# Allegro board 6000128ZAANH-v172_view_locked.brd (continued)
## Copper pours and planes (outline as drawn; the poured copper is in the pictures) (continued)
VDD_B on L4 (solid shape): 87.38,23.75 87.38,21.72 87.25,21.59 85.98,21.59 85.85,21.72 85.85,23.75 85.98,23.88 87.25,23.88
VDD_B on L5: 72.77,33.15 76.33,33.15 76.58,32.89 76.58,29.84 78.17,28.26 86.04,28.26 87.63,26.67 87.63,21.72 87.25,21.34 83.31,21.34 82.93,21.72 82.93,23.37 82.3,24 75.63,24 72.52,27.11 72.52,32.89
VSS on TOP (solid shape): 78.93,40.01 78.93,39.05 78.68,38.8 78.68,37.4 78.55,37.27 77.53,37.27 77.34,37.47 77.34,39.88 77.6,40.13 78.8,40.13
VSS on TOP (solid shape): 84.45,35.62 84.45,32 83.7,31.24 83.7,28.32 83.57,28.19 78.74,28.19 78.62,28.32 78.62,31.3 77.85,32.06 77.85,33.07 78.18,33.4 81.92,33.4 83.57,35.05 83.57,35.62 83.63,35.69 84.39,35.69
VSS on BOTTOM (solid shape): 82.49,20.45 87.25,20.45 87.38,20.32 87.38,17.65 87.19,17.46 76.26,17.46 76.01,17.72 76.01,19.94 76.2,20.13 78.49,20.13 78.74,20.38 78.74,20.64 78.87,20.76 82.17,20.76
VSS on L4 (solid shape): 87.38,20.32 87.38,18.29 87.25,18.16 85.98,18.16 85.85,18.29 85.85,20.32 85.98,20.45 87.25,20.45
VSS on BOTTOM, L2, L3, L4, L5: 77.34,39.88 77.34,37.47 77.53,37.27 83.18,37.27 83.57,36.88 83.57,35.05 81.92,33.4 78.87,33.4 78.61,33.15 78.61,29.84 78.8,29.65 84.26,29.65 84.46,29.85 84.46,40.19 84.38,40.26 77.72,40.26
VSS on L3: 78.61,30.23 84.45,30.23 84.45,21.46 84.96,20.95 87.38,20.95 87.63,20.7 87.63,17.65 87.38,17.4 81.66,17.4 80.52,18.54 80.52,25.65 78.61,27.56
EAR_GND on TOP (solid shape): 27.37,40.32 27.37,38.73 27.24,38.61 23.3,38.61 23.18,38.73 23.18,40.32 23.3,40.45 27.24,40.45
EAR_GND on TOP (solid shape): 31.11,61.15 31.11,59.69 30.92,59.5 29.78,59.5 29.59,59.69 29.59,61.15 29.78,61.34 30.92,61.34
EAR_GND on BOTTOM (solid shape): 31.37,61.09 31.37,36.45 31.24,36.32 29.97,36.32 28.07,38.23 21.34,38.23 20.07,39.5 20.07,43.56 20.32,43.82 22.22,43.82 22.48,43.56 22.48,41.4 23.37,40.51 28.7,40.51 29.84,41.66 29.84,58.36 28.38,59.82 26.16,59.82 22.29,55.94 20.51,55.94 20.19,56.26 20.19,57.02 20.45,57.28 21.59,57.28 25.65,61.34 31.11,61.34
MAIN_3V3 on TOP (solid shape): 40.01,65.53 39.88,65.41 39.18,65.41 39.05,65.53 39.05,68.63 40.01,68.63
PAIR12_FB23 on TOP (solid shape): 38.28,37.14 38.28,35.99 38.23,35.94 37.02,35.94 36.89,36.07 36.89,37.09 37.02,37.21 38.2,37.21
PAIR12_FB23 on BOTTOM (solid shape): 37.53,37.09 37.53,35.05 37.4,34.92 36.51,34.92 36.39,35.05 36.39,37.09 36.51,37.21 37.4,37.21
PAIR36_FB22 on TOP (solid shape): 38.28,43.74 38.28,42.6 38.23,42.55 37.02,42.55 36.89,42.67 36.89,43.69 37.02,43.82 38.2,43.82
PAIR36_FB22 on BOTTOM (solid shape): 37.53,43.69 37.53,41.79 37.4,41.66 36.51,41.66 36.39,41.79 36.39,43.69 36.51,43.82 37.4,43.82
PAIR45_FB21 on TOP (solid shape): 38.28,50.35 38.28,49.2 38.23,49.15 37.02,49.15 36.89,49.28 36.89,50.29 37.02,50.42 38.2,50.42
PAIR45_FB21 on BOTTOM (solid shape): 37.53,50.29 37.53,48.39 37.4,48.26 36.51,48.26 36.39,48.39 36.39,50.29 36.51,50.42 37.4,50.42
PAIR78_FB20 on TOP (solid shape): 38.28,56.95 38.28,55.81 38.23,55.76 37.02,55.76 36.89,55.88 36.89,56.9 37.02,57.03 38.2,57.03
PAIR78_FB20 on BOTTOM (solid shape): 37.53,56.9 37.53,54.99 37.4,54.87 36.51,54.87 36.39,54.99 36.39,56.9 36.51,57.03 37.4,57.03
POWER_IN on BOTTOM (solid shape): 93.15,70.8 93.15,66.48 93.09,66.42 91.57,66.42 91.38,66.23 88.71,66.23 88.39,66.55 88.39,70.74 88.65,70.99 92.96,70.99
POWER_IN on L2: 88.14,81.52 91.44,81.52 91.44,68.07 91.19,67.82 88.52,67.82 88.14,68.2
N5320670 on TOP (solid shape): 49.72,68.26 49.85,68.14 49.85,67.69 49.72,67.56 49.21,67.56 49.21,68.33 48.91,68.63 49.72,68.63
N17419443 on BOTTOM (solid shape): 91.5,65.41 93.09,65.41 93.15,65.34 93.15,63.18 93.09,63.12 91.76,63.12 91.69,63.18 91.69,63.88 91.38,64.2 88.96,64.2 88.84,64.33 88.84,65.47 88.96,65.6 91.31,65.6
N17426803 on BOTTOM (solid shape): 64.33,24.26 64.33,23.3 64.26,23.24 62.29,23.24 62.04,22.99 62.04,19.11 62.23,18.92 65.41,18.92 65.72,19.24 65.72,20.57 65.85,20.7 66.74,20.7 67.31,20.13 73.41,20.13 73.6,19.94 73.6,17.72 73.41,17.53 61.59,17.53 61.02,18.1 61.02,23.62 61.72,24.32 64.26,24.32
N17426807 on BOTTOM (solid shape): 65.6,27.69 65.6,25.46 66.48,24.57 73.41,24.57 73.6,24.38 73.6,22.03 73.47,21.91 67.31,21.91 66.74,21.34 62.42,21.34 62.29,21.46 62.29,22.54 62.36,22.61 64.33,22.61 64.58,22.86 64.58,26.92 64.33,27.18 62.36,27.18 62.29,27.24 62.29,28.32 62.36,28.38 64.9,28.38
N17432429 on BOTTOM (solid shape): 84.33,77.09 84.33,73.66 84.2,73.53 80.2,73.53 80.07,73.66 80.07,74.87 79.63,75.31 72.01,75.31 70.99,74.3 64.52,74.3 64.14,74.68 64.14,77.85 64.39,78.11 83.31,78.11
N17432448 on TOP (solid shape): 68.9,72.83 68.9,68.45 68.77,68.33 64.9,68.33 64.77,68.45 64.77,72.83 65.02,73.09 68.64,73.09
N17432448 on BOTTOM (solid shape): 71.88,70.99 73.53,70.99 73.66,70.87 73.66,69.72 73.53,69.6 64.39,69.6 64.26,69.72 64.26,72.71 64.64,73.09 69.79,73.09
N17432547 on BOTTOM (solid shape): 73.47,72.52 72.07,72.52 72.07,74.68 73.47,74.68
N17432813 on TOP (solid shape): 86.74,70.87 86.74,66.93 86.61,66.8 82.42,66.8 82.17,67.06 82.17,70.87 82.42,71.12 86.49,71.12
N17432813 on BOTTOM (solid shape): 84.33,72.9 84.33,70.87 84.71,70.48 86.49,70.48 86.74,70.23 86.74,66.67 86.49,66.42 80.9,66.42 80.77,66.55 80.77,72.9 80.9,73.03 84.2,73.03
N17439510 on TOP (solid shape): 71.38,40.9 71.12,40.64 66.04,40.64 65.79,40.39 65.79,39.62 65.47,39.31 63.75,39.31 63.63,39.43 63.63,44.07 63.75,44.2 67.64,44.2 69.09,45.65 69.09,47.81 69.79,48.5 69.79,51.69 71.38,51.69
N17439514 on TOP (solid shape): 82.49,46.1 82.49,44.39 82.11,44.01 81.41,44.01 80.14,42.74 77.47,42.74 77.41,42.8 77.41,44.58 77.47,44.64 78.8,44.64 79.12,44.96 79.12,46.03 79.25,46.15 82.43,46.15
N17439696 on TOP (solid shape): 83.82,51.56 83.82,49.53 84.52,48.83 85.47,48.83 85.53,48.77 85.53,48.2 85.47,48.13 84.14,48.13 83.76,48.51 72.39,48.51 72.39,51.69 83.69,51.69
N17439883 on TOP (solid shape): 78.36,47.74 78.36,45.59 78.17,45.4 74.1,45.4 73.15,44.45 72.01,44.45 71.88,44.57 71.88,47.82 71.95,47.88 78.22,47.88

Small or netless copper shapes (teardrops, artwork), in the pictures only: 4 on BOTTOM, 6 on TOP, 4 on L4

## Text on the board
Ref Des/Silkscreen Bottom: + | -
User.Comments: CR_3_1 | 3_5.5_3_G5.5 | 3.9_4.9_3.9_G7 | 4.7_5.3_4.7_G6.5 | The Layout file released by Mitrastar to | TI | Deliver data time: 2024/08/21 | MSTC confidential information and must be deleted in one-day after the review process is done. | to any third party without Mitrastar's prior written approval. | whether direct or indirect, suffered by Mitrastar. | shall not use or modify such Layout file for | Vender | any other purpose except the above or disclose the  Layout file | is for the sole purpose of "internal technical review" and for | Should | violate or breach aforementioned rule, | 5GNR01 | will be liable for any and all damages, | project only.
User.6: SLOT
User.30: FIGURE | FINISHED_SIZE | 8.0 | 10.0 | 12.0 | 36.0 | 41.0 | 52.0 | 130.0 | 166.0 | 30.0 | 32.0 | 44.0 | 63.0 | 157.0 | 48.0x24.0 | 63.0x24.0 | 91.0x40.0 | ROTATION | - | 90.000 | 0.000 | DRILL CHART: TOP to BOTTOM | ALL UNITS ARE IN MILS | TOLERANCE_DRILL | +3.0/-3.0 | +2.0/-2.0 | TOLERANCE_TRAVEL | PLATED | NON-PLATED | QTY | 53 | 745 | 1178 | 8 | 4 | 2 | 6 | 1 | 11 | 9 | 2035 | TOTAL HOLES:
